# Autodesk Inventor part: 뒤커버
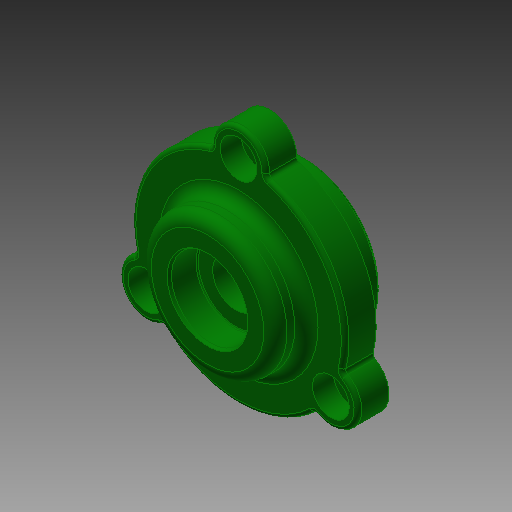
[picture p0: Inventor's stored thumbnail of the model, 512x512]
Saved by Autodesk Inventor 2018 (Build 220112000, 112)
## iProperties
Created: 2016-05
Part Number: 뒤커버
Document SubType Name: Modeling
Designer: mduedu
Density: 2.71 g/cm^3
Material: 알루미늄 6061
Appearance: 진녹색
Author: mduedu
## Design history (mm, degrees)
sketch "스케치1"
  geometry: C1 r 20 at (0, 0); C2 r 27.5 at (0, 0); 1 further point
  constraints: 2 centre point, 2 coincident
  dimensions: "d33" = 55 diameter of C2; "d34" = 40 diameter of C1
extrude "돌출1" new body sketch "스케치1" distance "d0" = 8; taper "d1" = 0 deg
extrude "돌출2" join sketch "스케치1" distance "d2" = 8; taper "d3" = 0 deg; dims "d35" = 9, "d36" = 0
sketch "스케치6"
  geometry: C1 r 17.5 at (0, 0); 2 further points
  constraints: 2 coincident, 1 centre point
  dimensions: "d42" = 35 diameter of C1
extrude "돌출4" join sketch "스케치6" distance "d43" = 8; taper "d44" = 0 deg
sketch "스케치4"
  geometry: L1 (0, -9)-(0, 16); L2 (-15, -9)-(-15, 0); L3 (-15, 0)-(-10, 0); L4 (-10, 0)-(-10, 3); L5 (-10, 3)-(-6, 3); L6 (-6, 3)-(-6, 8.7); L7 (-6, 8.7)-(-10, 8.7); L8 (-10, 8.7)-(-10, 16); L9 (20, -9)-(-20, -9) reference; L10 (17.5, 16)-(-17.5, 16) reference; 1 further point
  constraints: 16 end point, 6 parallel, 3 point on line, 2 midpoint, 2 perpendicular, 1 vertical
  dimensions: "d15" = 30 diameter of L2 L1; "d16" = 20 diameter of L8 L1; "d18" = 9 distance of L2.start L2.end; "d19" = 3 distance of L3.end L4.end; "d20" = 20 diameter of L4 L1; "d21" = 12 diameter of L6 L1; "d45" = 7.3 distance of L7.end L8.end
revolve "회전1" sketch "스케치4" stored, may be unused: angle "d22" = 90 deg
fillet "모깎기2" dims "d23" = 3
fillet "모깎기3" dims "d24" = 0.3
chamfer "모따기2" distance "d46" = 1; stored, may be unused: second distance "d47" = 2, angle "d48" = 45 deg
sketch "스케치7"
  geometry: C1 r 7 at (0, 27.5); 2 further points
  constraints: 3 vertical alignment, 1 centre point, 2 other
  dimensions: "d54" = 14 diameter of C1
extrude "돌출5" join sketch "스케치7" stored distance "d55" = 10; taper "d56" = 0 deg
fillet "모깎기6" dims "d57" = 1
sketch "스케치10"
  geometry: C1 r 17.5 at (0, 0) reference; A1 r 27.5 centre (0, 0) between (26.718, -6.513) and (7.718, 26.395) reference; A2 r 1 centre (7.999, 27.355) between (6.999, 27.373) and (7.718, 26.395) reference; A3 r 7 centre (0, 27.5) between (6.999, 27.373) and (-6.999, 27.373) reference; A4 r 1 centre (-7.999, 27.355) between (-7.718, 26.395) and (-6.999, 27.373) reference; A5 r 27.5 centre (0, 0) between (-7.718, 26.395) and (-26.718, -6.513) reference; A6 r 1 centre (-27.689, -6.75) between (-27.205, -7.625) and (-26.718, -6.513) reference; A7 r 7 centre (-23.816, -13.75) between (-27.205, -7.625) and (-20.206, -19.748) reference; A8 r 1 centre (-19.69, -20.604) between (-19, -19.881) and (-20.206, -19.748) reference; A9 r 27.5 centre (0, 0) between (-19, -19.881) and (19, -19.881) reference; A10 r 1 centre (19.69, -20.604) between (20.206, -19.748) and (19, -19.881) reference; A11 r 7 centre (23.816, -13.75) between (20.206, -19.748) and (27.205, -7.625) reference; A12 r 1 centre (27.689, -6.75) between (26.718, -6.513) and (27.205, -7.625) reference; 4 further points
  constraints: 3 coincident
hole "구멍3" sketch "스케치10" at (0, 27.5), (-23.816, -13.75), (23.816, -13.75) diameter "d81" = 5.5; stored, may be unused: countersink angle "d85" = 90 deg, drill point angle "d87" = 118 deg; dims "d82" = 6, "d83" = 9.5, "d84" = 5.4, "d86" = 8
fillet "모깎기7" dims "d61" = 1
fillet "모깎기8" dims "d88" = 3
chamfer "모따기3" distance "d76" = 0.7; stored, may be unused: second distance "d77" = 2, angle "d78" = 30 deg
node "솔리드1"
pattern_circular "원형 패턴1" dims angle "d59" = 360 deg
node "투영된 루프1"
